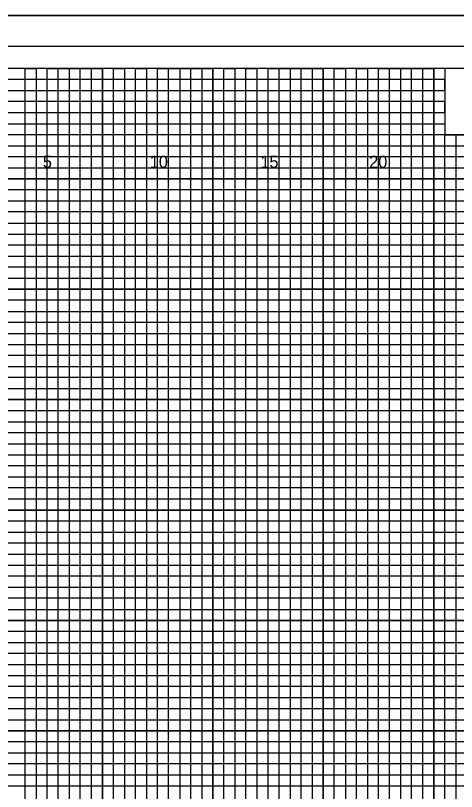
# Model space of a CAD drawing. Extents: x -4 to 103, y -2 to 351.
# Drawn here: x 54.82 to 74.78, y 103.08 to 138.22 of the extents above; entities that cross this region are included whole.
import ezdxf

# ---------------------------------------------------------------- set-up
doc = ezdxf.new("R2010")
doc.units = 0
for name, color, linetype in [('Old_Level_10', 7, 'Continuous'), ('Old_Level_16', 7, 'Continuous'), ('Old_Level_3', 7, 'Continuous'), ('Old_Level_4', 7, 'Continuous'), ('Old_Level_5', 7, 'Continuous'), ('Old_Level_6', 7, 'Continuous'), ('Old_Level_8', 7, 'Continuous'), ('Prop XS SE Text', 7, 'Continuous')]:
    doc.layers.add(name, color=color, linetype=linetype)

msp = doc.modelspace()

# ---------------------------------------------------------------- linework, layer by layer
at = {"layer": 'Old_Level_10'}
for p, q in [((56.25, 70.825), (56.25, 135.825)), ((58.75, 70.825), (58.75, 135.825)), ((61.25, 70.825), (61.25, 135.825)), ((63.75, 70.825), (63.75, 135.825)), ((66.25, 70.825), (66.25, 135.825)), ((68.75, 70.825), (68.75, 135.825)), ((71.25, 70.825), (71.25, 135.825)), ((73.75, 70.825), (73.75, 135.825)), ((0, 133.325), (74.25, 133.325)), ((0, 130.825), (102.5, 130.825)), ((0, 128.325), (102.5, 128.325)), ((0, 125.825), (102.5, 125.825)), ((0, 123.325), (102.5, 123.325)), ((0, 120.825), (102.5, 120.825)), ((0, 118.325), (102.5, 118.325)), ((0, 115.825), (102.5, 115.825)), ((0, 113.325), (102.5, 113.325)), ((0, 110.825), (102.5, 110.825)), ((0, 108.325), (102.5, 108.325)), ((0, 105.825), (102.5, 105.825)), ((0, 103.325), (102.5, 103.325))]:
    msp.add_line(p, q, dxfattribs=at)
at = {"layer": 'Old_Level_3'}
msp.add_line((-3.5, 138.225), (103.4, 138.225), dxfattribs=at)
at = {"layer": 'Old_Level_4'}
for points in [[(55.25, 70.825), (55.25, 135.825), (55.75, 135.825), (55.75, 70.825)], [(56.75, 70.825), (56.75, 135.825), (57.25, 135.825), (57.25, 70.825)], [(57.75, 70.825), (57.75, 135.825), (58.25, 135.825), (58.25, 70.825)], [(59.25, 70.825), (59.25, 135.825), (59.75, 135.825), (59.75, 70.825)], [(60.25, 70.825), (60.25, 135.825), (60.75, 135.825), (60.75, 70.825)], [(61.75, 70.825), (61.75, 135.825), (62.25, 135.825), (62.25, 70.825)], [(62.75, 70.825), (62.75, 135.825), (63.25, 135.825), (63.25, 70.825)], [(64.25, 70.825), (64.25, 135.825), (64.75, 135.825), (64.75, 70.825)], [(65.25, 70.825), (65.25, 135.825), (65.75, 135.825), (65.75, 70.825)], [(66.75, 70.825), (66.75, 135.825), (67.25, 135.825), (67.25, 70.825)], [(67.75, 70.825), (67.75, 135.825), (68.25, 135.825), (68.25, 70.825)], [(69.25, 70.825), (69.25, 135.825)], [(69.25, 135.825), (69.75, 135.825), (69.75, 70.825)], [(70.25, 70.825), (70.25, 135.825), (70.75, 135.825), (70.75, 70.825)], [(71.75, 70.825), (71.75, 135.825), (72.25, 135.825), (72.25, 70.825)], [(72.75, 70.825), (72.75, 135.825), (73.25, 135.825), (73.25, 70.825)], [(0, 132.825), (0, 133.825), (74.25, 133.825), (74.25, 134.325), (0, 134.325), (0, 134.825), (74.25, 134.825), (74.25, 135.325), (0, 135.325)], [(0, 132.325), (102.5, 132.325), (102.5, 132.825), (0, 132.825)], [(74.25, 70.825), (74.25, 132.825), (74.75, 132.825), (74.75, 70.825)], [(0, 131.325), (102.5, 131.325), (102.5, 131.825), (0, 131.825)], [(0, 129.825), (102.5, 129.825), (102.5, 130.325), (0, 130.325)], [(0, 128.825), (102.5, 128.825), (102.5, 129.325), (0, 129.325)], [(0, 127.325), (102.5, 127.325), (102.5, 127.825), (0, 127.825)], [(0, 126.325), (102.5, 126.325), (102.5, 126.825), (0, 126.825)], [(0, 124.825), (102.5, 124.825), (102.5, 125.325), (0, 125.325)], [(0, 123.825), (102.5, 123.825), (102.5, 124.325), (0, 124.325)], [(0, 122.325), (102.5, 122.325), (102.5, 122.825), (0, 122.825)], [(0, 121.325), (102.5, 121.325), (102.5, 121.825), (0, 121.825)], [(0, 119.825), (102.5, 119.825), (102.5, 120.325), (0, 120.325)], [(0, 118.825), (102.5, 118.825), (102.5, 119.325), (0, 119.325)], [(0, 117.325), (102.5, 117.325), (102.5, 117.825), (0, 117.825)], [(0, 116.325), (102.5, 116.325), (102.5, 116.825), (0, 116.825)], [(0, 114.825), (102.5, 114.825), (102.5, 115.325), (0, 115.325)], [(0, 113.825), (102.5, 113.825), (102.5, 114.325), (0, 114.325)], [(0, 112.325), (102.5, 112.325), (102.5, 112.825), (0, 112.825)], [(0, 111.325), (102.5, 111.325), (102.5, 111.825), (0, 111.825)], [(0, 109.825), (102.5, 109.825), (102.5, 110.325), (0, 110.325)], [(0, 108.825), (102.5, 108.825), (102.5, 109.325), (0, 109.325)], [(0, 107.325), (102.5, 107.325), (102.5, 107.825), (0, 107.825)], [(0, 106.325), (102.5, 106.325), (102.5, 106.825), (0, 106.825)], [(0, 104.825), (102.5, 104.825), (102.5, 105.325), (0, 105.325)], [(0, 103.825), (102.5, 103.825), (102.5, 104.325), (0, 104.325)]]:
    msp.add_lwpolyline(points, dxfattribs=at)
at = {"layer": 'Old_Level_5'}
msp.add_lwpolyline([(103.4, 138.225), (-3.5, 138.225), (-3.5, 68.4), (103.4, 68.4)], close=True, dxfattribs=at)
at = {"layer": 'Old_Level_6'}
for points in [[(102.5, 135.825), (0, 135.825), (0, 70.825), (102.5, 70.825)], [(83.75, 135.825), (74.25, 135.825), (74.25, 132.825), (83.75, 132.825)]]:
    msp.add_lwpolyline(points, close=True, dxfattribs=at)
at = {"layer": 'Old_Level_8'}
for points in [[(56.25, 70.825), (56.25, 135.825), (58.75, 135.825), (58.75, 70.825)], [(61.25, 70.825), (61.25, 135.825), (63.75, 135.825), (63.75, 70.825)], [(66.25, 70.825), (66.25, 135.825), (68.75, 135.825), (68.75, 70.825)], [(71.25, 70.825), (71.25, 135.825), (73.75, 135.825), (73.75, 70.825)], [(0, 133.325), (74.25, 133.325)], [(0, 128.325), (102.5, 128.325), (102.5, 130.825), (0, 130.825)], [(0, 123.325), (102.5, 123.325), (102.5, 125.825), (0, 125.825)], [(0, 118.325), (102.5, 118.325), (102.5, 120.825), (0, 120.825)], [(0, 113.325), (102.5, 113.325), (102.5, 115.825), (0, 115.825)], [(0, 108.325), (102.5, 108.325), (102.5, 110.825), (0, 110.825)], [(0, 103.325), (102.5, 103.325), (102.5, 105.825), (0, 105.825)]]:
    msp.add_lwpolyline(points, dxfattribs=at)
at = {"layer": 'Prop XS SE Text'}
msp.add_lwpolyline([(103, 136.825), (-2.8, 136.825), (-2.8, 69.825), (103, 69.825)], close=True, dxfattribs=at)

# ---------------------------------------------------------------- texts
at = {"layer": 'Old_Level_16'}
for s, p in [('5', (56.0574, 131.325)), ('10', (60.8971, 131.325)), ('15', (65.9057, 131.325)), ('20', (70.8312, 131.325))]:
    msp.add_text(s, height=0.55, dxfattribs=at).set_placement(p)

doc.saveas('drawing.dxf')
